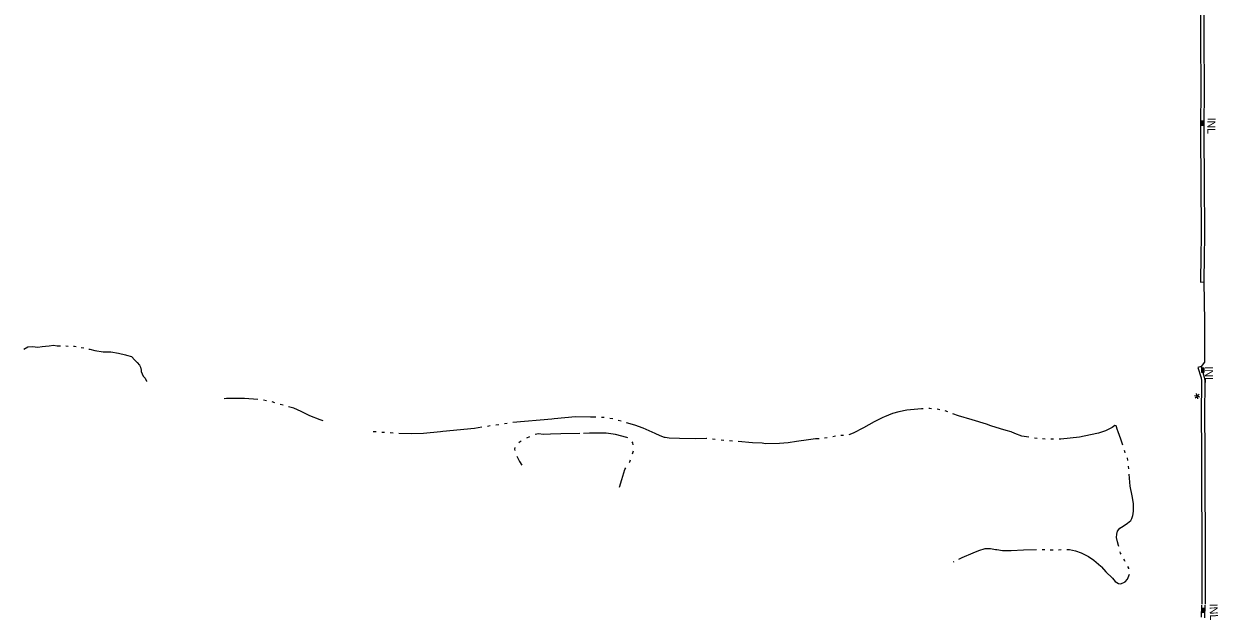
# Model space of a CAD drawing. Extents: x 588843 to 2552415, y 180129 to 269402.
# Drawn here: x 598325 to 599221, y 182929 to 183376 of the extents above; entities that cross this region are included whole.
import ezdxf

# ---------------------------------------------------------------- set-up
doc = ezdxf.new("R2010")
doc.units = 0
for name, color, linetype in [('E_DRN', 7, 'Continuous'), ('E_DRN_Text', 7, 'Continuous'), ('E_LTG', 7, 'Continuous'), ('E_RDWY', 7, 'Continuous'), ('E_RDWY_C_and_G', 7, 'Continuous'), ('E_WTR_P', 7, 'Continuous')]:
    doc.layers.add(name, color=color, linetype=linetype)

# ---------------------------------------------------------------- blocks, each defined once
blk = doc.blocks.new('LPOL_4')
at = {"layer": 'E_LTG'}
for p, q in [((-13.1, 0), (-4.9, 0)), ((-2.5, 4.3), (-6.6, 11.4)), ((2.5, 4.3), (6.6, 11.4)), ((4.9, 0), (13.1, 0)), ((-6.6, -11.4), (-2.5, -4.3)), ((6.6, -11.4), (2.5, -4.3))]:
    blk.add_line(p, q, dxfattribs=at)
for radius in [4.92, 4.92, 4.92, 0.41]:
    blk.add_circle((0, 0), radius, dxfattribs=at)
blk = doc.blocks.new('INLO_3')
at = {"layer": 'E_DRN'}
for p, q in [((6.6, -13.1), (6.6, 0)), ((13.1, -13.1), (13.1, 0)), ((19.7, -6.6), (0, -6.6))]:
    blk.add_line(p, q, dxfattribs=at)
blk.add_lwpolyline([(0, -13.1), (19.7, -13.1), (19.7, 0), (0, 0)], close=True, dxfattribs=at)
blk = doc.blocks.new('INLT_11_2')
at = {"layer": 'E_DRN_Text'}
blk.add_text('INL', height=39.37, dxfattribs=at).set_placement((-36.2, -19.7))
blk = doc.blocks.new('INLT_12_1')
at = {"layer": 'E_DRN_Text'}
blk.add_text('INL', height=39.37, dxfattribs=at).set_placement((-36.2, -19.7))

msp = doc.modelspace()

# ---------------------------------------------------------------- linework, layer by layer
at = {"layer": 'E_RDWY'}
msp.add_lwpolyline([(599209.96, 183182.08), (599210.42, 183152.56), (599210.55, 183122.01), (599207.95, 183118.73)], dxfattribs=at)
at = {"layer": 'E_RDWY_C_and_G'}
for points in [[(599207.37, 183446.65), (599207.4, 183422.42), (599207.52, 183392.94), (599207.46, 183361.38)], [(599209.87, 183446.65), (599209.9, 183422.43), (599210.02, 183392.95), (599209.96, 183361.38)], [(599207.46, 183361.38), (599207.76, 183329.93), (599207.58, 183294.99)], [(599209.96, 183361.4), (599210.26, 183329.94), (599210.08, 183294.98)], [(599207.58, 183294.99), (599207.74, 183254.62), (599208.01, 183221.57)], [(599210.08, 183295), (599210.24, 183254.63), (599210.51, 183221.59)], [(599208.01, 183221.57), (599207.66, 183196.39), (599207.49, 183187.69), (599207.46, 183182.05), (599209.96, 183182.08)], [(599210.5, 183221.54), (599210.16, 183196.35), (599209.99, 183187.66), (599209.96, 183182.03)], [(599207.95, 183118.73), (599205.55, 183118.01), (599207.86, 183110.3), (599208.11, 183108.04), (599208.09, 183082.34), (599208.17, 183056.02), (599208.32, 183025.73), (599208.37, 182993.44), (599208.39, 182965.86), (599208.35, 182940.43)], [(599207.95, 183118.73), (599210.32, 183110.8), (599210.61, 183108.18), (599210.59, 183082.34), (599210.67, 183056.03), (599210.82, 183025.74), (599210.87, 182993.45), (599210.89, 182965.86), (599210.85, 182940.42)], [(599208.23, 182939.86), (599207.94, 182930.73)], [(599210.72, 182939.78), (599210.42, 182930.18)]]:
    msp.add_lwpolyline(points, dxfattribs=at)
at = {"layer": 'E_WTR_P'}
for points in [[(598325.1, 183131.83), (598325.11, 183131.84), (598328.13, 183133.42), (598331.62, 183133.69), (598335.44, 183133.23), (598338.76, 183133.65), (598341.38, 183133.86), (598344.18, 183134.33), (598347.25, 183134.61), (598350.12, 183134.21), (598352.61, 183134.18)], [(598356.49, 183134.13), (598358.43, 183134.06)], [(598362.31, 183133.93), (598362.95, 183133.91), (598364.23, 183133.69)], [(598368.05, 183133.04), (598369.97, 183132.71)], [(598373.74, 183131.82), (598374.65, 183131.6), (598378.42, 183130.61), (598384.43, 183129.62), (598390.3, 183129.63), (598395.98, 183128.63), (598401.38, 183127.45)], [(598401.38, 183127.45), (598402.01, 183127.31), (598405.72, 183126.13), (598408.38, 183123.55), (598410.11, 183121.77), (598411.85, 183119.67), (598412.62, 183118.27), (598413.16, 183116.09), (598413.17, 183115.02), (598413.73, 183113.26), (598414.58, 183111.41), (598416.17, 183109.88), (598417.03, 183107.71), (598417.09, 183107.5)], [(598500.61, 183094), (598490.53, 183094.78), (598476.95, 183094.66), (598475.26, 183094.5)], [(598506.99, 183093.09), (598504.87, 183093.48)], [(598513.24, 183091.57), (598511.19, 183092.21)], [(598519.42, 183089.74), (598517.36, 183090.33)], [(598549.66, 183077.87), (598547.23, 183078.71), (598539.65, 183081.65), (598532.96, 183085.07), (598527.55, 183087.39), (598523.55, 183088.54)], [(598999.6, 183087.04), (598998.23, 183086.99), (598987.35, 183085.87), (598981.36, 183084.72), (598976.39, 183083.38), (598970.54, 183080.91)], [(599005.78, 183087.09), (599004.38, 183087.24), (599003.73, 183087.21)], [(599011.91, 183086.25), (599009.88, 183086.63)], [(599017.89, 183084.73), (599015.93, 183085.36)], [(599050.3, 183074.33), (599047.06, 183075.43), (599036.26, 183078.66), (599025.98, 183081.85), (599021.78, 183083.35)], [(598681.15, 183075.09), (598679.03, 183074.77)], [(598687.53, 183076.05), (598685.4, 183075.73)], [(598722.82, 183079.49), (598721.09, 183079.32), (598691.78, 183076.63)], [(598753.9, 183080.67), (598750.09, 183080.75), (598738.86, 183081.01), (598722.82, 183079.49)], [(598760.35, 183080.49), (598760.06, 183080.54), (598758.2, 183080.58)], [(598766.7, 183079.36), (598764.58, 183079.74)], [(598772.94, 183077.76), (598770.86, 183078.32)], [(598806.12, 183065.49), (598805.46, 183065.6), (598802.24, 183066.64), (598798.4, 183068.49), (598789.44, 183072.57), (598783.33, 183074.66), (598777.06, 183076.55)], [(598970.53, 183080.91), (598969.34, 183080.41), (598962.68, 183077.32), (598954.66, 183072.81), (598946.94, 183068.64), (598943.82, 183067.56)], [(599078.82, 183065.7), (599073.5, 183066.51), (599068.19, 183068.47), (599065.38, 183069.81), (599061.61, 183070.8), (599057.45, 183071.89), (599050.3, 183074.33)], [(599149.16, 183059.79), (599147.83, 183064.21), (599146.81, 183066.96), (599145.67, 183069.64), (599145.03, 183071.85), (599144.57, 183073.59), (599144.12, 183074.25), (599143.2, 183074.41), (599141.19, 183072.96), (599136.29, 183070.43), (599130.9, 183068.82)], [(598589.18, 183069.62), (598587.04, 183069.77)], [(598595.61, 183069.17), (598593.47, 183069.32)], [(598602.05, 183068.8), (598599.9, 183068.91)], [(598637.42, 183069.84), (598624.84, 183068.54), (598615.87, 183068.14), (598606.34, 183068.6)], [(598668.4, 183073.16), (598662.96, 183072.34), (598639.24, 183070.03), (598637.42, 183069.84)], [(598674.78, 183074.13), (598672.65, 183073.81)], [(598704.2, 183066.08), (598702.12, 183065.07)], [(598742.06, 183068.46), (598727.73, 183068.34), (598720.03, 183067.9), (598714.77, 183067.81), (598710.93, 183068.18), (598708.54, 183067.62)], [(598778.02, 183065.17), (598777.37, 183065.5), (598768.75, 183067.78), (598761.74, 183068.64), (598749.38, 183068.69), (598744.85, 183068.51)], [(598837.22, 183064.69), (598836.89, 183064.72), (598828.6, 183064.45), (598816.84, 183064.76), (598809.02, 183065), (598806.12, 183065.49)], [(598927.61, 183065.24), (598925.57, 183064.94)], [(598933.66, 183066.54), (598931.65, 183066.05)], [(598939.8, 183067.05), (598937.74, 183066.97)], [(599130.9, 183068.82), (599129.76, 183068.48), (599116.77, 183065.62), (599102.84, 183064.32), (599101.41, 183064.3)], [(598693.25, 183058.07), (598693.13, 183056.79), (598693.32, 183055.78)], [(598698.07, 183062.82), (598696.5, 183061.79), (598696.16, 183061.51)], [(598782.02, 183059.98), (598781.65, 183061.49), (598781.28, 183062.16)], [(598843.63, 183063.96), (598841.49, 183064.2)], [(598850.05, 183063.32), (598847.91, 183063.52)], [(598856.47, 183062.73), (598854.33, 183062.93)], [(598891.79, 183060.9), (598881.36, 183060.61), (598878.77, 183061.25), (598871.59, 183061.52), (598860.75, 183062.36)], [(598921.47, 183064.55), (598918.73, 183064.42), (598913.44, 183063.82), (598904.61, 183062.43), (598898.28, 183061.59), (598891.79, 183060.9)], [(599084.93, 183064.78), (599082.88, 183064.97)], [(599091.09, 183064.2), (599091.07, 183064.2), (599089.04, 183064.39)], [(599097.28, 183064.26), (599095.22, 183064.24)], [(598694.86, 183051.44), (598696.72, 183047.43), (598698.4, 183044.62)], [(598779.09, 183046.75), (598779.47, 183047.3), (598780.11, 183048.83)], [(598781.6, 183053.21), (598782.05, 183054.76), (598782.18, 183055.45)], [(599151.04, 183053.89), (599151.04, 183053.9), (599150.41, 183055.85)], [(599153.02, 183048.13), (599152.82, 183050.18)], [(598771.87, 183028.2), (598773.39, 183034.01), (598775.87, 183041.51), (598776.62, 183042.84)], [(599153.62, 183041.97), (599153.41, 183044.02)], [(599156.97, 183008.22), (599157.29, 183010.59), (599157.17, 183016.07), (599156.23, 183021.67), (599154.83, 183029.01), (599154.03, 183037.87)], [(599146.16, 182983.77), (599145.99, 182984.41), (599145.22, 182987.3), (599144.57, 182990.59), (599144.71, 182992.89), (599145.26, 182995.19), (599146.99, 182997.46), (599149.48, 182999.09), (599152.64, 183001.16), (599155.16, 183003.21), (599156.03, 183004.77), (599156.82, 183007.1), (599156.97, 183008.22)], [(599026.33, 182974.28), (599028.83, 182975.51), (599037, 182979.02), (599041.31, 182980.65), (599046.02, 182982.17), (599049.97, 182982.2), (599053.83, 182981.51), (599054.63, 182981.41)], [(599054.63, 182981.41), (599059.08, 182980.85), (599065.44, 182980.71), (599074.79, 182981.32), (599084.48, 182981.42)], [(599088.61, 182981.46), (599088.7, 182981.46), (599090.67, 182981.39)], [(599094.79, 182981.27), (599096.86, 182981.27)], [(599100.98, 182981.35), (599103.04, 182981.46)], [(599107.16, 182981.54), (599109.19, 182981.51), (599113.74, 182980.62), (599118.05, 182978.94), (599123.58, 182976.28), (599127.38, 182973.58), (599132.79, 182969.03), (599133.29, 182968.46)], [(599148, 182977.88), (599147.55, 182978.74), (599147.26, 182979.79)], [(599022.17, 182972.25), (599022.62, 182972.47)], [(599133.29, 182968.46), (599136.56, 182964.74), (599141.39, 182960.03), (599143.57, 182957.59), (599145.97, 182955.94), (599147.83, 182955.72), (599151.04, 182957.24), (599152.68, 182959.22), (599153.71, 182961.7), (599154.14, 182962.97)], [(599150.9, 182972.41), (599150.39, 182973.43), (599149.95, 182974.25)], [(599153.8, 182966.97), (599153.61, 182967.6), (599152.87, 182968.79)]]:
    msp.add_lwpolyline(points, dxfattribs=at)

# ---------------------------------------------------------------- block references
at = {"layer": 'E_DRN'}
for p, xscale, yscale, rotation in [((599210.12, 183302.61), 0.1524003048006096, 0.15240030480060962, -90.29493105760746), ((599210.23, 183117.53), 0.1524003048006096, 0.15240030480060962, -90.29493105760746), ((599210.65, 182937.44), 0.1524003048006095, 0.15240030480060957, -87.70075244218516)]:
    msp.add_blockref('INLO_3', p, dxfattribs=dict(at, xscale=xscale, yscale=yscale, rotation=rotation))
at = {"layer": 'E_DRN_Text'}
for name, p, xscale, yscale, rotation in [('INLT_11_2', (599215.7, 183299.88), 0.1524003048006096, 0.15240030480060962, -90.29493105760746), ('INLT_11_2', (599213.91, 183113.27), 0.1524003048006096, 0.15240030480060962, -90.29493105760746), ('INLT_12_1', (599217.41, 182935.37), 0.1524003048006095, 0.15240030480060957, -87.70075244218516)]:
    msp.add_blockref(name, p, dxfattribs=dict(at, xscale=xscale, yscale=yscale, rotation=rotation))
at = {"layer": 'E_LTG', "xscale": 0.1524003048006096, "yscale": 0.1524003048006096, "rotation": -16.127348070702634}
msp.add_blockref('LPOL_4', (599204.94, 183096.53), dxfattribs=at)

doc.saveas('drawing.dxf')
